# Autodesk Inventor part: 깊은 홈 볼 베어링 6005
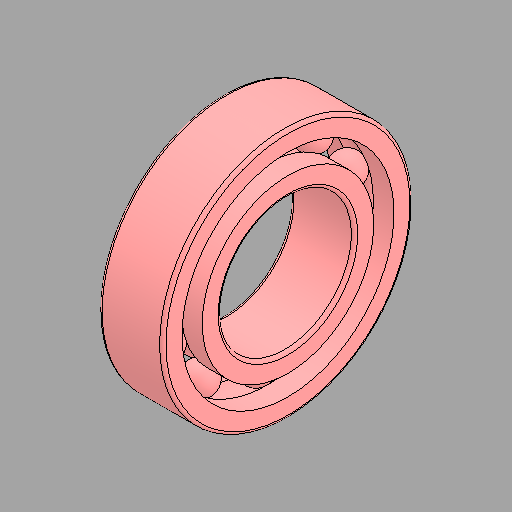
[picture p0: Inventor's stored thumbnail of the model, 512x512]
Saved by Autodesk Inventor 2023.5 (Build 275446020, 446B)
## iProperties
Created: 2025-07
Part Number: 깊은 홈 볼 베어링 6005
Material: 강철, 연강
Description: 깊은 그루브 볼 베어링
Document SubType Name: Modeling
Designer: 1강의실14
Density: 7.85 g/cm^3
Appearance: 기본값
Author: jhkim
Sending System: Autodesk Inventor 2026
Preprocessor: ST-DEVELOPER v20.1
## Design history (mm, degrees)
feature "Solid1"
feature "Solid1:1"
feature "Solid1:2"
feature "Solid1:3"
feature "Solid1:4"
feature "Solid1:5"
feature "Solid1:6"
feature "Solid1:7"
feature "Solid1:8"
feature "Solid1:9"
feature "Solid1:10"
feature "Solid1:11"
node "솔리드1"
node "솔리드2"
node "솔리드3"
node "솔리드4"
node "솔리드5"
node "솔리드6"
node "솔리드7"
node "솔리드8"
node "솔리드9"
node "솔리드10"
node "솔리드11"
node "솔리드12"
